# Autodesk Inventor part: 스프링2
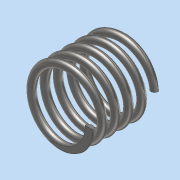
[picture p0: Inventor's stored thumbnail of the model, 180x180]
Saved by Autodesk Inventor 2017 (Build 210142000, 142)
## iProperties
Part Number: 스프링2
Material: 스테인레스 스틸
Document SubType Name: Modeling
Designer: MRC
Density: 8 g/cm^3
Appearance: 반연마
Mass: 6.54895 g
Surface Area: 16.6959 cm^2
Volume: 0.818619 cm^3
Author: MRC
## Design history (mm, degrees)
sketch "스케치1"
  geometry: L1 (0, 0)-(0, 17.5); L2 (0, 17.5)-(20.921, 17.5); L3 (0, 0)-(8.5, 0); C1 r 1 at (8.5, 0)
  constraints: 6 end point, 2 horizontal, 1 centre point, 1 coincident, 1 vertical
  dimensions: "d0" = 17.5 distance of L1.start L1.end (derived); "d1" = 8.5 distance of L1.start L3.end; "d2" = 2 diameter of C1
feature "코일1" sketch "스케치1" pitch "d3" = 10; turns "d5" = 5; dims "d4" = 17.5 (= d0), "d6" = 0, angle "d7" = 90 deg, angle "d8" = 90 deg, "d9" = 0, "d10" = 0
sketch "스케치2"
  geometry: L1 (17.5, 11.939)-(0, 11.939); L2 (0, 11.939)-(0, -12.02); L3 (0, -12.02)-(17.5, -12.02); L4 (17.5, -12.02)-(17.5, 11.939); 1 further point
  constraints: 8 end point, 2 parallel, 1 horizontal, 1 perpendicular, 1 point on line
  dimensions: "d11" = 17.5 distance of L2.end L3.end (= d0)
extrude "돌출1" sketch "스케치2" stored distance "d12" = 0; taper "d13" = 0 deg
node "솔리드1"
